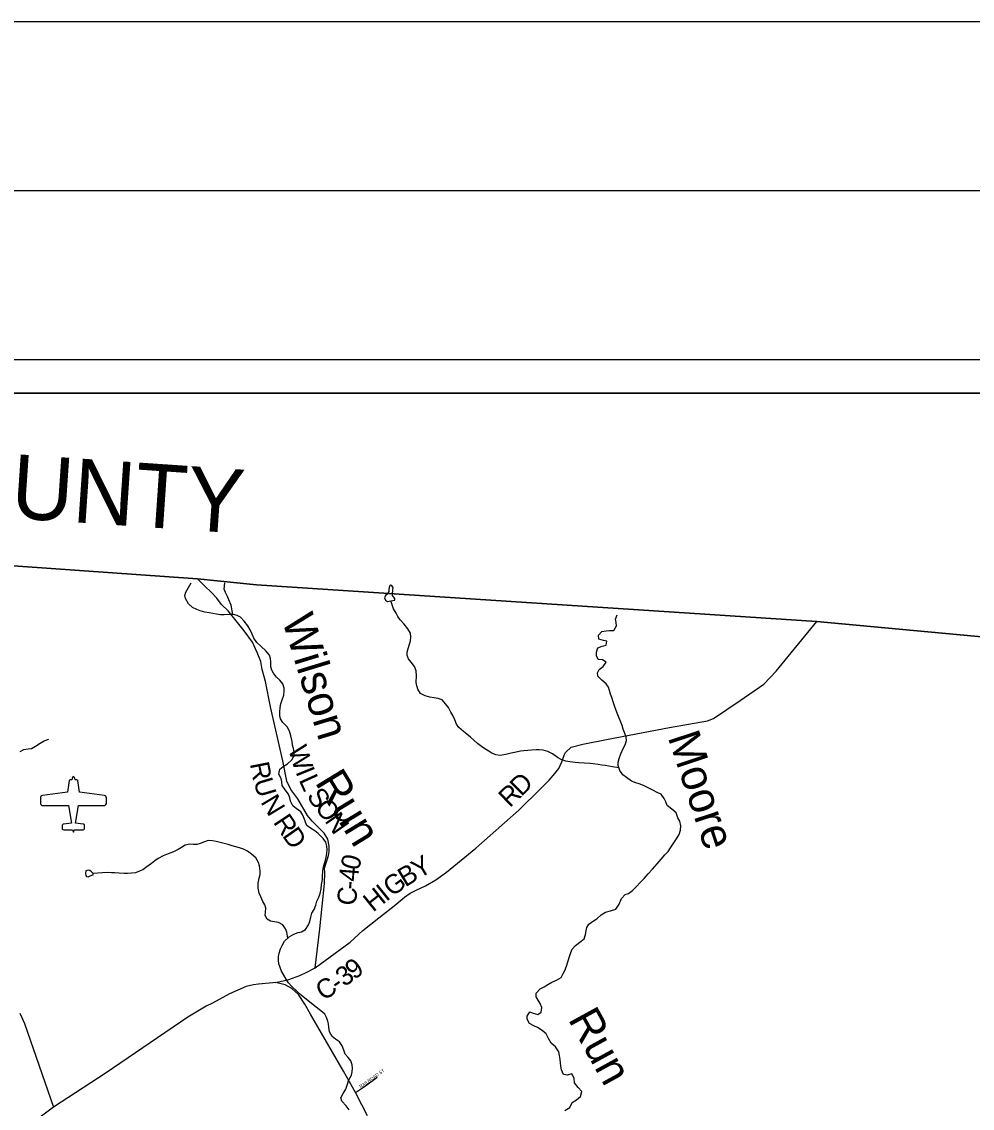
# Model space of a CAD drawing. Extents: x 0 to 34, y 0 to 22.
# Drawn here: x 25.527 to 28.342, y 18.782 to 22 of the extents above; entities that cross this region are included whole.
import ezdxf

# ---------------------------------------------------------------- set-up
doc = ezdxf.new("R2010")
doc.units = 0
for name, color, linetype in [('GM_X_Adjacent_County', 7, 'Continuous'), ('GM_X_Adjacent_County_Text', 7, 'Continuous'), ('GM_X_Airport_Class_3', 7, 'Continuous'), ('GM_X_Airport_Location_Class_3', 7, 'Continuous'), ('GM_X_County', 7, 'Continuous'), ('GM_X_County_Road', 7, 'Continuous'), ('GM_X_County_Road_Text', 7, 'Continuous'), ('GM_X_Minor_Lake', 7, 'Continuous'), ('GM_X_Minor_River', 7, 'Continuous'), ('GM_X_Minor_River_Text', 7, 'Continuous'), ('GM_X_State_Route', 7, 'Continuous'), ('GM_X_Township', 7, 'Continuous'), ('GM_X_Township_Subdivision', 7, 'Continuous'), ('GM_X_Township_Subdivision_Text', 7, 'Continuous'), ('SH_Border', 7, 'Continuous'), ('SH_Cut_Line', 7, 'Continuous'), ('SH_Data', 7, 'Continuous')]:
    doc.layers.add(name, color=color, linetype=linetype)

msp = doc.modelspace()

# ---------------------------------------------------------------- linework, layer by layer
at = {"layer": 'GM_X_Adjacent_County'}
for points in [[(30.8167, 19.9966), (30.8167, 20.9), (24.0167, 20.9), (24.0167, 20.4902)], [(24.0167, 20.4902), (25.2637, 20.4053), (26.0476, 20.3502), (26.2222, 20.3325), (27.8816, 20.224), (28.5075, 20.1657), (30.3764, 20.0297), (30.5069, 20.0201), (30.8167, 19.9966)]]:
    msp.add_lwpolyline(points, dxfattribs=at)
at = {"layer": 'GM_X_Airport_Class_3'}
for points in [[(25.6799, 19.7648), (25.6785, 19.7642), (25.6769, 19.7619), (25.6758, 19.7585), (25.6751, 19.755), (25.6701, 19.755), (25.6681, 19.7543), (25.6671, 19.7529), (25.662, 19.718), (25.5879, 19.7085), (25.5846, 19.7071), (25.5834, 19.7057), (25.5824, 19.7023), (25.5823, 19.6851), (25.5835, 19.6814), (25.5866, 19.6791), (25.6649, 19.6786), (25.6739, 19.6266), (25.6509, 19.624), (25.6496, 19.6237), (25.6475, 19.6219), (25.647, 19.6207), (25.6467, 19.6112), (25.647, 19.6097), (25.6487, 19.6074), (25.6514, 19.6064), (25.6775, 19.6064), (25.6799, 19.6003)], [(25.6799, 19.6003), (25.6823, 19.6064), (25.7084, 19.6064), (25.7112, 19.6074), (25.7129, 19.6097), (25.7131, 19.6112), (25.7129, 19.6207), (25.7123, 19.6219), (25.7102, 19.6237), (25.7089, 19.624), (25.6859, 19.6266), (25.695, 19.6786), (25.7732, 19.6791), (25.7763, 19.6814), (25.7775, 19.6851), (25.7775, 19.7023), (25.7764, 19.7057), (25.7752, 19.7071), (25.772, 19.7085), (25.6978, 19.718), (25.6928, 19.7529), (25.6917, 19.7543), (25.6898, 19.755), (25.6847, 19.755), (25.6841, 19.7585), (25.6829, 19.7619), (25.6814, 19.7642), (25.6799, 19.7648)]]:
    msp.add_lwpolyline(points, dxfattribs=at)
at = {"layer": 'GM_X_Airport_Location_Class_3'}
msp.add_line((25.6799, 19.6871), (25.6799, 19.6871), dxfattribs=at)
at = {"layer": 'GM_X_County'}
msp.add_lwpolyline([(30.8167, 19.9966), (30.5069, 20.0201), (30.3764, 20.0297), (28.5075, 20.1657), (27.8816, 20.224), (26.2222, 20.3325), (26.0476, 20.3502), (25.2637, 20.4053), (24.0167, 20.4902)], dxfattribs=at)
at = {"layer": 'GM_X_County_Road'}
for points in [[(26.3955, 19.1984), (26.4101, 19.3133), (26.4236, 19.4483), (26.4249, 19.4798), (26.4235, 19.4931), (26.4277, 19.506), (26.4319, 19.5177), (26.4358, 19.5306), (26.4374, 19.5424), (26.4371, 19.5583), (26.433, 19.5788), (26.4221, 19.5967), (26.4048, 19.6143), (26.3871, 19.6322), (26.3736, 19.649), (26.345, 19.6989), (26.324, 19.7259), (26.312, 19.751), (26.2998, 19.8111), (26.2632, 19.9711), (26.2492, 20.0459), (26.2388, 20.0821), (26.2348, 20.1056), (26.2239, 20.1322), (26.2105, 20.1623), (26.1857, 20.1966), (26.1383, 20.2553), (26.1183, 20.2737), (26.105, 20.2927), (26.0875, 20.3102), (26.0695, 20.3282), (26.0476, 20.3502)], [(26.2797, 19.1545), (26.3179, 19.1632), (26.3507, 19.1758), (26.3716, 19.1848), (26.3955, 19.1984), (26.4251, 19.2195), (26.4992, 19.2745), (26.5373, 19.3084), (26.584, 19.3457), (26.6346, 19.3853), (26.6601, 19.4072), (26.6775, 19.4193), (26.695, 19.4286), (26.7227, 19.441), (26.7535, 19.4591), (26.785, 19.4817), (26.8713, 19.5522), (26.9995, 19.6646), (27.0646, 19.7296), (27.0886, 19.7541), (27.1061, 19.7734), (27.1179, 19.7889), (27.126, 19.8086), (27.1329, 19.8279), (27.1378, 19.8362), (27.1538, 19.8517), (27.1887, 19.8606), (27.2641, 19.875), (27.4453, 19.9097), (27.5582, 19.9296), (27.5757, 19.9367), (27.6551, 19.9902), (27.7243, 20.0381), (27.7609, 20.077), (27.8816, 20.224)], [(25.5213, 19.0641), (25.5348, 19.0333), (25.6207, 18.7858)]]:
    msp.add_lwpolyline(points, dxfattribs=at)
at = {"layer": 'GM_X_Minor_Lake'}
for points in [[(26.6094, 20.3047), (26.6055, 20.3016), (26.6029, 20.2986), (26.6009, 20.2941), (26.6042, 20.2872), (26.6103, 20.2834), (26.6205, 20.2851), (26.6323, 20.2873), (26.6323, 20.2918), (26.6278, 20.2965), (26.6249, 20.301), (26.6252, 20.3033)], [(26.6252, 20.3033), (26.6258, 20.3186), (26.6266, 20.3247), (26.6233, 20.3296), (26.6203, 20.3312), (26.6172, 20.3301), (26.6153, 20.3244), (26.6144, 20.318), (26.614, 20.3127), (26.6094, 20.3047)], [(25.738, 19.4778), (25.7335, 19.4824), (25.7286, 19.4859), (25.7252, 19.4875), (25.7206, 19.4868), (25.7172, 19.4849), (25.716, 19.4773), (25.7163, 19.4716), (25.7185, 19.4686), (25.7234, 19.4678), (25.728, 19.4696), (25.7341, 19.4722)], [(25.7341, 19.4722), (25.7385, 19.4739), (25.7385, 19.4748), (25.738, 19.4778)]]:
    msp.add_lwpolyline(points, dxfattribs=at)
at = {"layer": 'GM_X_Minor_River'}
for points in [[(26.4207, 19.4973), (26.4242, 19.5102), (26.4286, 19.5253), (26.4306, 19.5374), (26.4311, 19.548), (26.4305, 19.5587), (26.4272, 19.5705), (26.4198, 19.5812), (26.4044, 19.5962), (26.3946, 19.6039), (26.3818, 19.612), (26.3717, 19.6193), (26.3669, 19.6296), (26.3629, 19.6407), (26.3592, 19.6506), (26.3532, 19.6602), (26.3401, 19.6702), (26.33, 19.6783), (26.3225, 19.6913), (26.3208, 19.7019), (26.3171, 19.7126), (26.307, 19.7256), (26.2977, 19.7379), (26.2971, 19.7485), (26.2949, 19.7584), (26.2879, 19.7714), (26.2914, 19.7869), (26.301, 19.7944), (26.3136, 19.8026), (26.3266, 19.8142), (26.334, 19.8274), (26.3341, 19.8373), (26.332, 19.8472), (26.329, 19.8575), (26.328, 19.8681), (26.3237, 19.8849), (26.3204, 19.8986), (26.313, 19.912), (26.2999, 19.9243), (26.2928, 19.9357), (26.2914, 19.9456), (26.2916, 19.9551), (26.2925, 19.9695), (26.2945, 19.9801), (26.2981, 19.9922), (26.3028, 20.0058), (26.304, 20.0172), (26.3038, 20.0267), (26.3001, 20.0393), (26.2916, 20.05), (26.2818, 20.0592), (26.2721, 20.0704), (26.2677, 20.0799), (26.2651, 20.0894), (26.2645, 20.1043), (26.2639, 20.1141), (26.2602, 20.124), (26.2494, 20.1367), (26.2359, 20.1498), (26.2232, 20.1617), (26.2146, 20.1747), (26.2091, 20.1858), (26.2032, 20.1991), (26.1965, 20.2114), (26.1861, 20.2251), (26.1748, 20.2367), (26.165, 20.2417), (26.1541, 20.2445), (26.1412, 20.2446), (26.1264, 20.2433), (26.1154, 20.2434), (26.1033, 20.2451), (26.0821, 20.2491), (26.0689, 20.2519), (26.0553, 20.2555), (26.0455, 20.259), (26.0323, 20.2653), (26.0207, 20.2764), (26.0118, 20.2917), (26.0104, 20.3012), (26.0132, 20.311), (26.0209, 20.3246), (26.0283, 20.3378)], [(26.1522, 20.2445), (26.1476, 20.2723), (26.1406, 20.2879), (26.1358, 20.2983), (26.1302, 20.3097), (26.1262, 20.32), (26.1281, 20.3383)], [(27.2956, 19.7906), (27.2768, 19.7937), (27.2658, 19.7957), (27.2548, 19.797), (27.245, 19.7983), (27.234, 19.8007), (27.2196, 19.8024), (27.209, 19.8032), (27.1939, 19.8046), (27.1769, 19.8055), (27.1663, 19.8064), (27.15, 19.8081), (27.1383, 19.8098), (27.1247, 19.8148), (27.1138, 19.821), (27.0984, 19.8315), (27.0848, 19.8392), (27.0716, 19.8428), (27.0595, 19.8437), (27.05, 19.8434), (27.0367, 19.8428), (27.0257, 19.8418), (27.014, 19.8408), (27.0045, 19.8398), (26.9916, 19.8369), (26.976, 19.8337), (26.9642, 19.8308), (26.9543, 19.8286), (26.9437, 19.8272), (26.9308, 19.8285), (26.9188, 19.8339), (26.9086, 19.8409), (26.8988, 19.8471), (26.8883, 19.854), (26.8763, 19.8629), (26.8654, 19.8725), (26.8557, 19.8814), (26.8455, 19.8902), (26.835, 19.8979), (26.8219, 19.9095), (26.8148, 19.9202), (26.8093, 19.9328), (26.8034, 19.9458), (26.7982, 19.9557), (26.7908, 19.9687), (26.7822, 19.9802), (26.7725, 19.9921), (26.76, 19.996), (26.7479, 19.9977), (26.7355, 20.0001), (26.7215, 20.0037), (26.7083, 20.0103), (26.6997, 20.0237), (26.6968, 20.0336), (26.6951, 20.0435), (26.696, 20.0632), (26.6947, 20.0776), (26.6899, 20.091), (26.6802, 20.1029), (26.672, 20.1132), (26.6684, 20.1228), (26.6685, 20.133), (26.6716, 20.144), (26.6756, 20.1565), (26.6784, 20.1663), (26.6796, 20.1788), (26.6779, 20.1891), (26.6701, 20.2025), (26.66, 20.2159), (26.6473, 20.2286), (26.6406, 20.2385), (26.6362, 20.2481), (26.6284, 20.2611), (26.6205, 20.2851)], [(27.2432, 19.3553), (27.2558, 19.3631), (27.2706, 19.3671), (27.2859, 19.3723), (27.2959, 19.3869), (27.3033, 19.4036), (27.3136, 19.4156), (27.3235, 19.4181), (27.3357, 19.4267), (27.3473, 19.4387), (27.3584, 19.4504), (27.3699, 19.4628), (27.3826, 19.4767), (27.3948, 19.4902), (27.4087, 19.5063), (27.421, 19.5195), (27.4317, 19.5323), (27.4409, 19.5424), (27.4482, 19.5533), (27.456, 19.5654), (27.4664, 19.5801), (27.4737, 19.5933), (27.4777, 19.6058), (27.479, 19.6187), (27.4761, 19.632), (27.4701, 19.6423), (27.4654, 19.6568), (27.4522, 19.6683), (27.4387, 19.6787), (27.4343, 19.6894), (27.4299, 19.6997), (27.4202, 19.7123), (27.4089, 19.717), (27.3957, 19.724), (27.3844, 19.7302), (27.3686, 19.738), (27.3557, 19.7431), (27.3459, 19.7462), (27.3327, 19.7509), (27.3181, 19.7614), (27.3075, 19.7694), (27.2982, 19.7821), (27.2935, 19.7973), (27.2936, 19.8068), (27.2964, 19.8178), (27.3011, 19.8318), (27.3081, 19.8473), (27.3143, 19.8586), (27.3175, 19.8715), (27.3172, 19.881), (27.3117, 19.8954), (27.308, 19.9054), (27.3047, 19.9153), (27.3011, 19.9259), (27.2967, 19.9374), (27.2926, 19.9477), (27.2878, 19.9599), (27.2827, 19.9744), (27.2787, 19.9862), (27.2743, 19.9988), (27.271, 20.0083), (27.2677, 20.019), (27.2648, 20.0296), (27.2573, 20.0396), (27.2446, 20.0496), (27.2326, 20.0623), (27.2323, 20.0718), (27.2366, 20.0816), (27.2489, 20.0902), (27.2574, 20.103), (27.2465, 20.1104), (27.2336, 20.1116), (27.2288, 20.122), (27.2293, 20.1326), (27.2332, 20.1454), (27.2458, 20.1506), (27.2576, 20.1539), (27.2593, 20.166), (27.2494, 20.1677), (27.2362, 20.1712), (27.2352, 20.183), (27.2448, 20.1943), (27.2577, 20.1964), (27.2672, 20.1967), (27.2801, 20.1973), (27.2882, 20.2113), (27.2876, 20.2212), (27.2858, 20.2307), (27.2905, 20.2439)], [(25.522, 19.8387), (25.5327, 19.8446), (25.546, 19.8464), (25.5559, 19.8478), (25.5677, 19.8541), (25.5811, 19.8638), (25.5936, 19.8705), (25.6073, 19.8749)], [(26.3146, 19.2861), (26.3116, 19.3034), (26.3083, 19.3134), (26.3001, 19.3256), (26.2876, 19.3322), (26.2755, 19.3346), (26.2638, 19.3363), (26.254, 19.3421), (26.2477, 19.3532), (26.2486, 19.3634), (26.2502, 19.3748), (26.2466, 19.3843), (26.2414, 19.3942), (26.2351, 19.4083), (26.2303, 19.4194), (26.2271, 19.4342), (26.2268, 19.449), (26.2304, 19.4638), (26.2328, 19.4744), (26.2329, 19.4843), (26.2312, 19.5002), (26.2279, 19.5105), (26.2205, 19.5243), (26.2078, 19.5343), (26.1954, 19.5436), (26.1841, 19.5494), (26.172, 19.5537), (26.1614, 19.5568), (26.1501, 19.5596), (26.138, 19.5632), (26.1267, 19.5664), (26.1146, 19.5695), (26.1025, 19.5723), (26.0923, 19.5744), (26.0794, 19.5749), (26.0684, 19.5712), (26.0554, 19.5664), (26.0452, 19.5635), (26.0349, 19.5636), (26.0247, 19.5645), (26.011, 19.5616), (26.0003, 19.5549), (25.9904, 19.549), (25.9767, 19.5419), (25.9603, 19.5356), (25.9462, 19.5297), (25.9314, 19.5215), (25.9214, 19.5152), (25.9115, 19.507), (25.8977, 19.4969), (25.8851, 19.4887), (25.8752, 19.4839), (25.8634, 19.4798), (25.8517, 19.4784), (25.8403, 19.4778), (25.8301, 19.4779), (25.8153, 19.4789), (25.8028, 19.4794), (25.7926, 19.4799), (25.7801, 19.48), (25.7664, 19.4798), (25.738, 19.4778)], [(26.4969, 18.7775), (26.4875, 18.7894), (26.4752, 18.8028), (26.4719, 18.8131), (26.4785, 18.8263), (26.487, 18.8391), (26.492, 18.8535), (26.4952, 18.8664), (26.5033, 18.8799), (26.5057, 18.8901), (26.5066, 18.9011), (26.506, 18.9106), (26.5016, 18.9228), (26.4937, 18.9324), (26.4851, 18.9428), (26.4811, 18.9542), (26.4763, 18.9675), (26.4681, 18.9786), (26.4561, 18.9871), (26.4459, 18.9948), (26.4381, 19.009), (26.436, 19.0227), (26.435, 19.0325), (26.4332, 19.0405), (26.4299, 19.0512), (26.4243, 19.0607), (26.4127, 19.0711), (26.3988, 19.0812), (26.3849, 19.0927), (26.3541, 19.1174), (26.3425, 19.1277), (26.326, 19.1435), (26.3174, 19.1538), (26.3103, 19.1642), (26.3029, 19.176), (26.2958, 19.1882), (26.2918, 19.1989), (26.2885, 19.21), (26.2875, 19.221), (26.2876, 19.2312), (26.2889, 19.2411), (26.2936, 19.2543), (26.2978, 19.2641), (26.3048, 19.2766), (26.3186, 19.2901), (26.3323, 19.2979), (26.3453, 19.3031), (26.3551, 19.3052), (26.3673, 19.3112), (26.3766, 19.3251), (26.3805, 19.3357), (26.3829, 19.3486), (26.3865, 19.3603), (26.3934, 19.3708), (26.3981, 19.3841), (26.4009, 19.3954), (26.4067, 19.4075), (26.411, 19.4181), (26.4138, 19.4317), (26.4151, 19.445), (26.418, 19.4597), (26.4177, 19.4692), (26.4183, 19.4856), (26.4207, 19.4973)], [(27.1358, 18.7758), (27.1503, 18.7848), (27.1569, 18.7991), (27.1695, 18.8069), (27.1817, 18.8171), (27.1857, 18.8314), (27.1744, 18.8441), (27.164, 18.8575), (27.163, 18.8712), (27.1563, 18.8841), (27.1434, 18.8805), (27.1313, 18.8822), (27.1254, 18.8963), (27.1232, 18.9073), (27.1222, 18.9168), (27.1219, 18.9267), (27.1198, 18.9388), (27.1173, 18.9491), (27.1076, 18.964), (27.0952, 18.9752), (27.0859, 18.9905), (27.08, 19.0027), (27.0684, 19.0123), (27.0541, 19.0216), (27.0435, 19.0266), (27.0311, 19.0332), (27.0236, 19.0458), (27.0234, 19.0553), (27.0318, 19.0674), (27.0417, 19.0642), (27.0549, 19.0603), (27.0656, 19.067), (27.0676, 19.0803), (27.0625, 19.0928), (27.0561, 19.1024), (27.0509, 19.1127), (27.0507, 19.1233), (27.0622, 19.1361), (27.074, 19.142), (27.0851, 19.1484), (27.0965, 19.1554), (27.1106, 19.1617), (27.124, 19.1696), (27.1294, 19.1797), (27.1356, 19.1899), (27.1399, 19.2028), (27.145, 19.219), (27.1493, 19.2315), (27.1532, 19.2432), (27.1575, 19.253), (27.1667, 19.2643), (27.1797, 19.2737), (27.1927, 19.2841), (27.1963, 19.2966), (27.1983, 19.3076), (27.2007, 19.3174), (27.2069, 19.3272), (27.2203, 19.3377), (27.2306, 19.3437), (27.2432, 19.3553)]]:
    msp.add_lwpolyline(points, dxfattribs=at)
at = {"layer": 'GM_X_State_Route'}
for points in [[(26.2797, 19.1545), (26.2701, 19.1536), (26.2278, 19.1498), (26.2129, 19.1478), (26.1913, 19.1432), (26.142, 19.1207), (26.0916, 19.0936), (26.0731, 19.0844), (26.0185, 19.0516), (25.7741, 18.8849), (25.6207, 18.7858), (25.5574, 18.7385)], [(26.5511, 18.7602), (26.5343, 18.7924), (26.5156, 18.8285), (26.4798, 18.8918), (26.3821, 19.0609), (26.3651, 19.0905), (26.3466, 19.1195), (26.3273, 19.1373), (26.3067, 19.1481), (26.2797, 19.1545)]]:
    msp.add_lwpolyline(points, dxfattribs=at)
at = {"layer": 'GM_X_Township'}
msp.add_lwpolyline([(30.8167, 19.9966), (30.5069, 20.0201), (30.3764, 20.0297), (28.5075, 20.1657), (27.8816, 20.224), (26.2222, 20.3325), (26.0476, 20.3502), (25.2637, 20.4053), (24.0167, 20.4902)], dxfattribs=at)
at = {"layer": 'GM_X_Township_Subdivision'}
msp.add_lwpolyline([(26.5156, 18.8285), (26.5388, 18.8444), (26.5487, 18.8516), (26.5794, 18.8741)], dxfattribs=at)
at = {"layer": 'SH_Border'}
msp.add_lwpolyline([(2, 21.5), (33.5, 21.5), (33.5, 0.5), (2, 0.5)], close=True, dxfattribs=at)
at = {"layer": 'SH_Cut_Line'}
msp.add_lwpolyline([(0, 0), (34, 0), (34, 22), (0, 22)], close=True, dxfattribs=at)
at = {"layer": 'SH_Data'}
for points in [[(23.9167, 21), (30.9167, 21), (30.9167, 14), (23.9167, 14)], [(24.0167, 20.9), (30.8167, 20.9), (30.8167, 14.1), (24.0167, 14.1)]]:
    msp.add_lwpolyline(points, close=True, dxfattribs=at)

# ---------------------------------------------------------------- texts
at = {"layer": 'GM_X_Adjacent_County_Text'}
msp.add_text('ROSS COUNTY', height=0.189394, rotation=356.0927, dxfattribs=at).set_placement((24.3263, 20.6104))
at = {"layer": 'GM_X_County_Road_Text'}
for s, rotation, p in [('W', 287.4498, (26.3153, 19.8463)), ('R', 281.1071, (26.2023, 19.8027)), ('I', 292.0958, (26.3368, 19.7787)), ('U', 286.5268, (26.2127, 19.7513)), ('L', 294.4985, (26.3466, 19.7547)), ('D', 44.9778, (27.0069, 19.7035)), ('S', 304.0413, (26.3692, 19.7071)), ('R', 43.6945, (26.9722, 19.6703)), ('N', 301.058, (26.2331, 19.6892)), ('O', 307.1142, (26.3926, 19.6726)), ('R', 303.7428, (26.2701, 19.6293)), ('N', 304.9884, (26.4225, 19.6332)), ('D', 305.0367, (26.2967, 19.5894)), ('0', 76.0458, (26.525, 19.4844)), ('Y', 30.9713, (26.7027, 19.4603)), ('B', 31.2516, (26.6628, 19.4361)), ('4', 85.5514, (26.5227, 19.4519)), ('G', 36.6739, (26.6239, 19.407)), ('C', 84.355, (26.5163, 19.3807)), ('-', 85.8682, (26.521, 19.4287)), ('H', 38.9511, (26.5673, 19.3613)), ('I', 38.867, (26.6062, 19.3927)), ('9', 36.6774, (26.5111, 19.1611)), ('3', 36.3885, (26.4827, 19.1402)), ('C', 31.3848, (26.4194, 19.0993)), ('-', 35.5751, (26.463, 19.1261))]:
    msp.add_text(s, height=0.0568, rotation=rotation, dxfattribs=at).set_placement(p)
at = {"layer": 'GM_X_Minor_River_Text'}
for s, height, rotation, p in [('Wilson', 0.09473, 287.0187, (26.297, 20.2297)), ('Moore', 0.09472, 288.2887, (27.4396, 19.8815)), ('Run', 0.09471, 301.3898, (26.3935, 19.7479)), ('Run', 0.09471, 298.756, (27.1435, 19.0463))]:
    msp.add_text(s, height=height, rotation=rotation, dxfattribs=at).set_placement(p)
at = {"layer": 'GM_X_Township_Subdivision_Text'}
msp.add_text('RAILROAD ST', height=0.00947, rotation=35.6134, dxfattribs=at).set_placement((26.5312, 18.8412))

doc.saveas('drawing.dxf')
